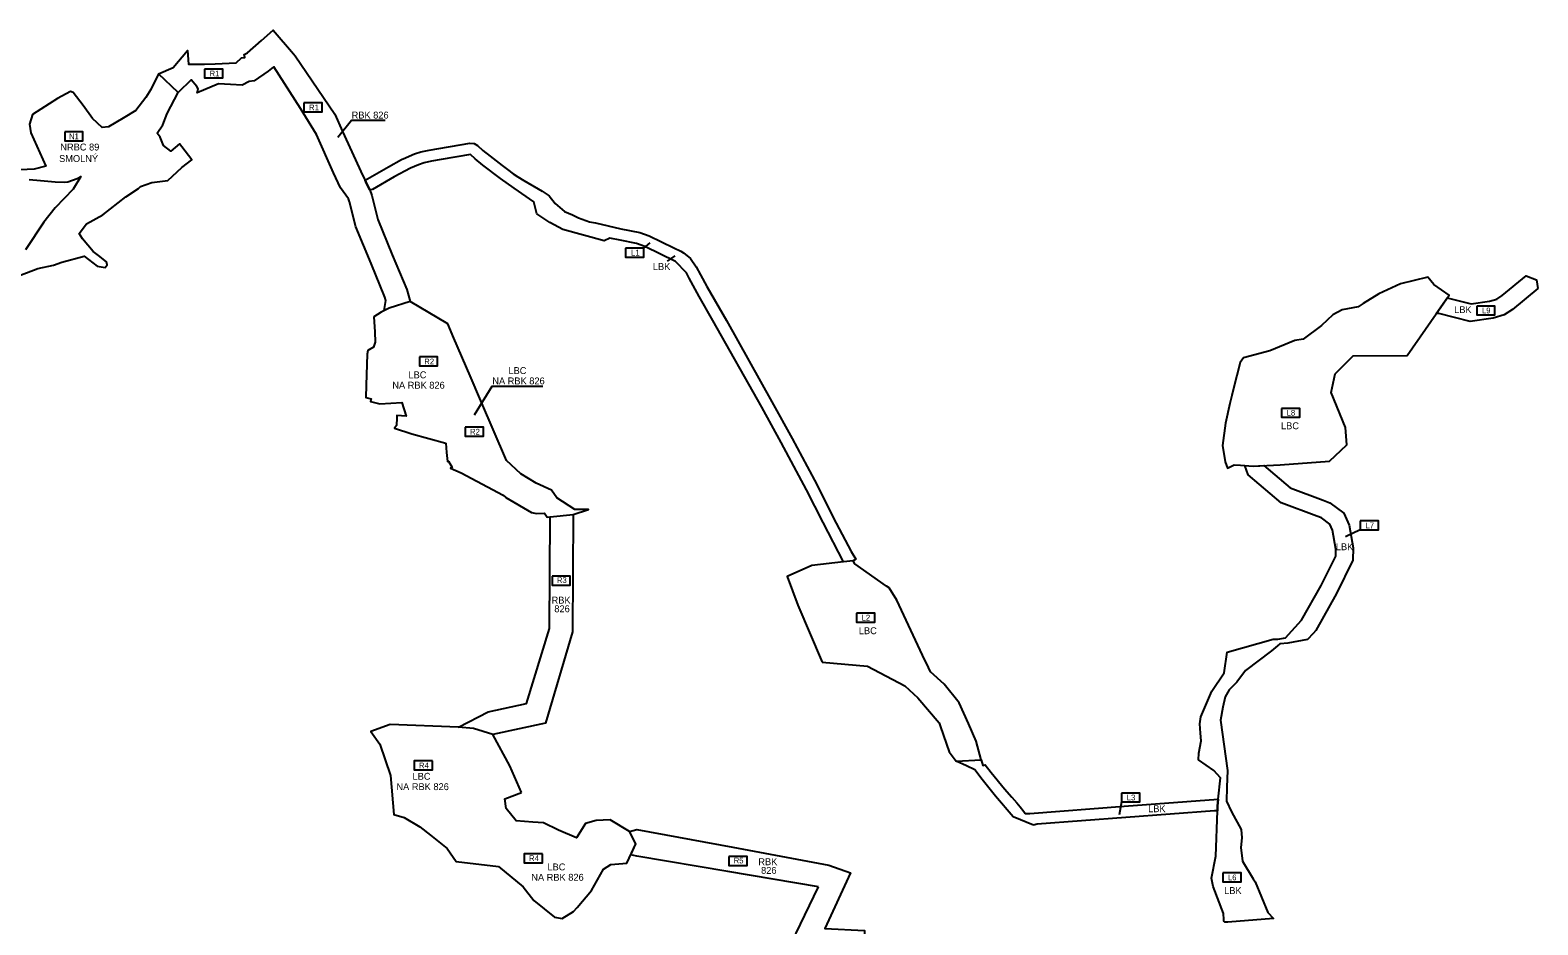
# Model space of a CAD drawing. Extents: x -546680 to -530218, y -1046521 to -1035695.
# Drawn here: x -542866 to -540248, y -1039689 to -1038135 of the extents above; entities that cross this region are included whole.
import ezdxf

# ---------------------------------------------------------------- set-up
doc = ezdxf.new("R2010")
doc.units = 0
for name, color, linetype in [('Vrstva 1', 7, 'Continuous'), ('Vrstva 18', 7, 'Continuous'), ('Vrstva 3', 7, 'Continuous'), ('Vrstva 30', 7, 'Continuous'), ('Vrstva 32', 7, 'Continuous'), ('Vrstva 33', 7, 'Continuous'), ('Vrstva 54', 7, 'Continuous'), ('Vrstva 82', 7, 'Continuous')]:
    doc.layers.add(name, color=color, linetype=linetype)

msp = doc.modelspace()

# ---------------------------------------------------------------- linework, layer by layer
at = {"layer": 'Vrstva 1'}
for points in [[(-542284.6, -1038396.1), (-542281.8, -1038401.7), (-542276.2, -1038412.8), (-542273, -1038422.6), (-542262.3, -1038464.5), (-542237.2, -1038525.6), (-542212.2, -1038585.7), (-542206.1, -1038606.5), (-542242.4, -1038618.3), (-542251.3, -1038622.5), (-542248.6, -1038604.8), (-542250, -1038599), (-542274.2, -1038540.9), (-542300.4, -1038477.1), (-542311.4, -1038433.8), (-542313.3, -1038428.1), (-542327.3, -1038409.3), (-542339.6, -1038383.2), (-542368.8, -1038316.9), (-542373.5, -1038309.2), (-542396.7, -1038271.2), (-542442.8, -1038198.9), (-542447, -1038202.1), (-542452.7, -1038206.8), (-542477.2, -1038223.2), (-542485.5, -1038224.6), (-542497.7, -1038230.9), (-542517.9, -1038229.8), (-542539.1, -1038228.8), (-542575.9, -1038244.5), (-542574.6, -1038237.3), (-542576.9, -1038233.4), (-542586.4, -1038221.8), (-542609.3, -1038243.8), (-542643.3, -1038211.5), (-542617.8, -1038200.5), (-542592.9, -1038170.8), (-542591.4, -1038194.5), (-542563.3, -1038194.5), (-542544.9, -1038193.7), (-542532.5, -1038193.1), (-542508.5, -1038192), (-542499.2, -1038183.2), (-542493.2, -1038183.1), (-542494.5, -1038177.9), (-542488.9, -1038174.9), (-542464.4, -1038153.3), (-542443.9, -1038135.4), (-542408.6, -1038176.6), (-542405.7, -1038180.1), (-542337.2, -1038281.4), (-542323.5, -1038311.4), (-542288.5, -1038388.2), (-542284.6, -1038396.1)], [(-542096.2, -1039348.1), (-542122.5, -1039345.9), (-542070.9, -1039319.5), (-542004.1, -1039304.9), (-541964.5, -1039174.3), (-541963.4, -1038980.4), (-541923.4, -1038976.8), (-541924, -1039078.6), (-541924.5, -1039180.3), (-541971.5, -1039338.7), (-542062.4, -1039358.6), (-542096.2, -1039348.1)], [(-541497.1, -1039623), (-541654.8, -1039596.4), (-541812.4, -1039569.9), (-541823.3, -1039567.6), (-541814.2, -1039548.4), (-541825.5, -1039527.1), (-541812.7, -1039523.3), (-541645.9, -1039554.4), (-541479.1, -1039585.5)], [(-541479.1, -1039585.5), (-541441.9, -1039599), (-541486, -1039695.6), (-541417.4, -1039699), (-541415.9, -1039747.1)], [(-541453, -1039757.1), (-541455.7, -1039732.7), (-541528.6, -1039734), (-541536.3, -1039704.6), (-541497.1, -1039623)]]:
    msp.add_lwpolyline(points, dxfattribs=at)
at = {"layer": 'Vrstva 18'}
for points in [[(-542884.3, -1038561.6), (-542852.6, -1038549.6), (-542825.5, -1038543.5), (-542811.2, -1038538.3), (-542772.5, -1038528.2), (-542749.6, -1038545.1), (-542735.8, -1038547.6), (-542732.4, -1038543), (-542733.3, -1038537.6), (-542747.2, -1038527), (-542756.6, -1038519.9), (-542775.1, -1038497.6), (-542781, -1038488.8), (-542768.4, -1038471.7), (-542739.9, -1038456.2), (-542700.2, -1038425.1), (-542677.8, -1038410.5), (-542674.6, -1038406.9), (-542654.7, -1038399.7), (-542626.9, -1038396.7), (-542602.8, -1038374), (-542585.5, -1038360.9), (-542602.6, -1038338), (-542606.6, -1038332.6), (-542621.9, -1038345.8), (-542634.5, -1038335.7), (-542640.1, -1038321.4), (-542645.3, -1038314.1), (-542635.8, -1038300), (-542628.4, -1038280), (-542609.3, -1038243.8), (-542643.3, -1038211.5), (-542656.6, -1038238.4), (-542665.1, -1038252.2), (-542682.8, -1038275.2), (-542704.4, -1038288.3), (-542730.3, -1038303.1), (-542740.8, -1038304.5), (-542757.6, -1038289.1), (-542774.1, -1038266.4), (-542791.2, -1038243.5), (-542796.1, -1038241.8), (-542818.6, -1038253.9), (-542862.1, -1038281.8), (-542867.4, -1038298.6), (-542864.8, -1038313.5), (-542838.9, -1038371.7), (-542859.1, -1038376.6), (-542883.4, -1038378)], [(-542867.8, -1038394.6), (-542847.8, -1038396.5), (-542822.6, -1038398.8), (-542806, -1038399.4), (-542800.4, -1038398.7), (-542784.3, -1038392.8), (-542778.1, -1038389.6), (-542791.3, -1038411.4), (-542822.9, -1038444.2), (-542842.2, -1038469), (-542873.9, -1038517.1)]]:
    msp.add_lwpolyline(points, dxfattribs=at)
at = {"layer": 'Vrstva 3'}
msp.add_line((-541759.3, -1038536.4), (-541746.1, -1038527.2), dxfattribs=at)
for points in [[(-542249.8, -1038292.3), (-542308.3, -1038292.3), (-542331.8, -1038321.8)], [(-541975.6, -1038754), (-542064.4, -1038754), (-542095.1, -1038803.9)]]:
    msp.add_lwpolyline(points, dxfattribs=at)
at = {"layer": 'Vrstva 30'}
for points in [[(-542563.2, -1038202.9), (-542563.2, -1038218.4), (-542531.5, -1038218.4), (-542531.5, -1038202.9), (-542563.2, -1038202.9)], [(-542390.6, -1038261.9), (-542390.6, -1038277.4), (-542358.9, -1038277.4), (-542358.9, -1038261.9), (-542390.6, -1038261.9)], [(-542806.1, -1038312), (-542806.1, -1038327.5), (-542774.4, -1038327.5), (-542774.4, -1038312), (-542806.1, -1038312)], [(-541959.9, -1039083.5), (-541959.9, -1039099), (-541928.2, -1039099), (-541928.2, -1039083.5), (-541959.9, -1039083.5)], [(-541652.9, -1039570.6), (-541652.9, -1039586.2), (-541621.2, -1039586.2), (-541621.2, -1039570.6), (-541652.9, -1039570.6)]]:
    msp.add_lwpolyline(points, dxfattribs=at)
at = {"layer": 'Vrstva 32'}
for points in [[(-540764.3, -1038890.9), (-540742.5, -1038892.4), (-540695.8, -1038890.1), (-540609.7, -1038884.2), (-540579.7, -1038855.5), (-540581.9, -1038825.5), (-540607.2, -1038764.7), (-540599.9, -1038732), (-540568.7, -1038701.1), (-540475, -1038700.3), (-540402.2, -1038595.5), (-540429, -1038577), (-540439.3, -1038564.1), (-540486.8, -1038575.7), (-540524.1, -1038593.1), (-540551.3, -1038610.1), (-540560.2, -1038615.7), (-540588, -1038621.1), (-540604.4, -1038629.6), (-540623.7, -1038648.1), (-540655.8, -1038671.8), (-540670.3, -1038674.4), (-540713.8, -1038692.2), (-540759.5, -1038704.5), (-540765.3, -1038712.8), (-540776.5, -1038757.7), (-540779.5, -1038769.7), (-540783, -1038784), (-540790.8, -1038818.1), (-540795.5, -1038856.8), (-540791.1, -1038885.2), (-540787.2, -1038896), (-540778.9, -1038891.8), (-540775.6, -1038890.1), (-540764.3, -1038890.9)], [(-542144.5, -1038852.9), (-542143, -1038869), (-542141.5, -1038884.4), (-542139.7, -1038884.2), (-542133.2, -1038895.2), (-542136.2, -1038896.3), (-542117.8, -1038904.3), (-542044.9, -1038943.2), (-542039.9, -1038946.9), (-541995.5, -1038972.9), (-541986.7, -1038974.7), (-541973, -1038974.4), (-541968.5, -1038980.9), (-541963.4, -1038980.4), (-541923.4, -1038976.8), (-541896.5, -1038968.1), (-541920.4, -1038968.1), (-541951.5, -1038947.8), (-541960.6, -1038934.5), (-541987.3, -1038921.9), (-542013.8, -1038905.7), (-542038.9, -1038882.8), (-542083.5, -1038779.2), (-542102.2, -1038735.7), (-542130.3, -1038670.2), (-542140.9, -1038645.5), (-542206.1, -1038606.5), (-542242.4, -1038618.3), (-542256.8, -1038625.1), (-542269.1, -1038633.3), (-542267.3, -1038659.4), (-542267.2, -1038677), (-542270, -1038686.2), (-542279.7, -1038691.8), (-542280.9, -1038698.3), (-542282.4, -1038752.2), (-542283, -1038773.4), (-542274.1, -1038775.9), (-542274.9, -1038780.5), (-542258.9, -1038784.2), (-542220.8, -1038782.2), (-542213, -1038805.8), (-542229.1, -1038804.6), (-542229.3, -1038808.6), (-542230.1, -1038821.9), (-542233.7, -1038826.6), (-542203.2, -1038836.2), (-542144.5, -1038852.9)], [(-541508.8, -1039064.9), (-541551.8, -1039084.4), (-541533.2, -1039134.2)], [(-541379.1, -1039101.1), (-541434.1, -1039062.1), (-541437.3, -1039057.1), (-541453.7, -1039058.9), (-541508.8, -1039064.9)], [(-541316.4, -1039221), (-541361.3, -1039125.5), (-541374.8, -1039104.1), (-541379.1, -1039101.1)], [(-541533.2, -1039134.2), (-541490.9, -1039233.1)], [(-541490.9, -1039233.1), (-541411.9, -1039239.8), (-541347.4, -1039274.2), (-541324.8, -1039295.1)], [(-541306.5, -1039242.1), (-541316.4, -1039221)], [(-541223.6, -1039370.3), (-541236.9, -1039339.5), (-541253, -1039303.7), (-541278.9, -1039271.4), (-541303, -1039249.5), (-541306.5, -1039242.1)], [(-541324.8, -1039295.1), (-541287.8, -1039338.2), (-541285.6, -1039345.3), (-541270.3, -1039388.7), (-541258, -1039405.2), (-541214.8, -1039402.4), (-541223.6, -1039370.3)], [(-542012.9, -1039459.2), (-542033.1, -1039412.8), (-542062.4, -1039358.6), (-542096.2, -1039348.1), (-542122.5, -1039345.9), (-542241, -1039341.3), (-542274.7, -1039353.4), (-542259, -1039375.2), (-542240.4, -1039429.6), (-542234.7, -1039497.8), (-542216.8, -1039502.6), (-542189.2, -1039518.9), (-542170.7, -1039533.6)], [(-542052.9, -1039587.9), (-542010.1, -1039623.4), (-541991.3, -1039646.9), (-541955.5, -1039676.1), (-541942.2, -1039678.2), (-541922.5, -1039665.9), (-541916.1, -1039658.8), (-541891.1, -1039629.8), (-541870.4, -1039592.2), (-541857.7, -1039584.2), (-541830.3, -1039582.2), (-541814.2, -1039548.4), (-541825.5, -1039527.1), (-541858.7, -1039507), (-541883.2, -1039508.2), (-541901.9, -1039513.1), (-541917.7, -1039537.9), (-541948.9, -1039524.7), (-541974.5, -1039511.9), (-541993.3, -1039510.6), (-542022.2, -1039508.8), (-542039.7, -1039487.1), (-542041.8, -1039470.2), (-542012.9, -1039459.2)], [(-542170.7, -1039533.6), (-542141.8, -1039556.7), (-542126.6, -1039579.4), (-542052.9, -1039587.9)]]:
    msp.add_lwpolyline(points, dxfattribs=at)
at = {"layer": 'Vrstva 33'}
msp.add_lwpolyline([(-542271.9, -1038411.9), (-542276.2, -1038412.8), (-542281.8, -1038401.7), (-542284.6, -1038396.1), (-542244, -1038372.8), (-542221.3, -1038360.3), (-542214.6, -1038356.9), (-542208.2, -1038354), (-542198.6, -1038350.4), (-542187.9, -1038346.8), (-542173.2, -1038343.6), (-542102.7, -1038331.6), (-542094.9, -1038332.4), (-542089.2, -1038335.5), (-542080, -1038344.3), (-542067.6, -1038354.4), (-542046.5, -1038370.4), (-542037.5, -1038377.2), (-542027.3, -1038384.7), (-542019.1, -1038390.4), (-542009.1, -1038396.7), (-541977.1, -1038415.3), (-541965, -1038422.9), (-541954.2, -1038436.3), (-541938.1, -1038450.1), (-541924.4, -1038456), (-541913.7, -1038461.6), (-541894.6, -1038468.1), (-541884.7, -1038470.1), (-541840.2, -1038480.7), (-541807.7, -1038486.8), (-541791.1, -1038492.6), (-541748.3, -1038513.3), (-541736.4, -1038519.3), (-541731.5, -1038522), (-541719.5, -1038531.9), (-541709.7, -1038546.4), (-541701.9, -1038560.1), (-541690.9, -1038580.8), (-541656.7, -1038639.9), (-541578, -1038780.7), (-541543.2, -1038844.3), (-541516.7, -1038893.1), (-541500.1, -1038924.3), (-541471.5, -1038981.6), (-541440.4, -1039040.7), (-541432.5, -1039054.2), (-541437.3, -1039057.1), (-541453.7, -1039058.9), (-541489.3, -1038990.7), (-541517.8, -1038933.5), (-541562.1, -1038851.5), (-541595.5, -1038790.4), (-541680.7, -1038639.6), (-541704.3, -1038597.8), (-541721.8, -1038565.9), (-541726.7, -1038557), (-541745.8, -1038536.9), (-541798.7, -1038511.1), (-541813.1, -1038506.1), (-541841.4, -1038500.3), (-541859.4, -1038496.6), (-541869.1, -1038501.1), (-541940.9, -1038481.6), (-541963.9, -1038469.4), (-541986.1, -1038454.4), (-541991.4, -1038433.3), (-542025.7, -1038409.7), (-542049.4, -1038393.3), (-542080.1, -1038370.1), (-542093.5, -1038359.1), (-542101.4, -1038351.5), (-542152.6, -1038360.2), (-542169.3, -1038363.2), (-542181.8, -1038366), (-542192, -1038369.3), (-542205.9, -1038375), (-542234.2, -1038390.3)], close=True, dxfattribs=at)
for points in [[(-540248.2, -1038584.2), (-540292.3, -1038620.3), (-540306.7, -1038629.8), (-540325.5, -1038635.7), (-540365.7, -1038641.2), (-540420.3, -1038627.3), (-540424.6, -1038627.6), (-540405.5, -1038600.1), (-540363.9, -1038610.6), (-540332.1, -1038606.3), (-540319.7, -1038602.4), (-540310.1, -1038596.1), (-540268.5, -1038562.1), (-540250.7, -1038568.9), (-540248.2, -1038584.2)], [(-540707.8, -1039193), (-540699.8, -1039193.1), (-540686.2, -1039190.9), (-540658.3, -1039160.2), (-540624.3, -1039100), (-540599.2, -1039048.7), (-540598.7, -1039036.7), (-540604.9, -1039004), (-540609.6, -1038993.3), (-540624.1, -1038982.5), (-540631.9, -1038979.4), (-540693.8, -1038956.2), (-540750.9, -1038907.8), (-540756.8, -1038891.4), (-540742.5, -1038892.4), (-540723.8, -1038891.5), (-540678.3, -1038930), (-540621, -1038951.4), (-540609.4, -1038956.1), (-540585.3, -1038974), (-540576.1, -1038995.1), (-540568.6, -1039034.4), (-540569.4, -1039056.1), (-540597.7, -1039114), (-540633.8, -1039177.9), (-540638.4, -1039183), (-540648.4, -1039193.9), (-540682.1, -1039200), (-540695.5, -1039201.1), (-540696.4, -1039201.2), (-540700.5, -1039204.7), (-540710.4, -1039213.2), (-540756.1, -1039247.6), (-540770.9, -1039268), (-540784.1, -1039281.3), (-540791, -1039293.4), (-540795.1, -1039311), (-540799.2, -1039334), (-540787.1, -1039421.4), (-540788, -1039450.1), (-540789, -1039474.2), (-540780.2, -1039493), (-540763.2, -1039523.7), (-540762.2, -1039537.8), (-540764.2, -1039554.8), (-540761.1, -1039578.7), (-540742.5, -1039609.1), (-540739.3, -1039614.4), (-540717.3, -1039667.5), (-540707.2, -1039678.1), (-540786.5, -1039684.4), (-540791.7, -1039684.8), (-540792.7, -1039683.6), (-540793.4, -1039682.3), (-540793.6, -1039679.6), (-540794, -1039669.3), (-540812, -1039622.7), (-540814.7, -1039607.9), (-540807.6, -1039569.8), (-540804.7, -1039490.9), (-540804.4, -1039482.9), (-540803.1, -1039470.7), (-540799.1, -1039433.7), (-540810.6, -1039420.9), (-540837.7, -1039402.8), (-540837.1, -1039390.9), (-540832.8, -1039369.8), (-540833.9, -1039356.4), (-540835.2, -1039340.1), (-540833.1, -1039327.7), (-540814.2, -1039283.2), (-540792.6, -1039251.5), (-540787.8, -1039215.8), (-540707.8, -1039193)], [(-541240.5, -1039413.2), (-541258, -1039405.2), (-541214.8, -1039402.4), (-541212.1, -1039412.2), (-541207.8, -1039411), (-541197.2, -1039424.8), (-541174.4, -1039453.2), (-541161.6, -1039467.4), (-541152.8, -1039477.5), (-541147.2, -1039484.2), (-541140.9, -1039492.3), (-541138.3, -1039496)], [(-541124.1, -1039516.3), (-541159.3, -1039501.5), (-541189.8, -1039465.9), (-541213, -1039437), (-541225.8, -1039419.9), (-541240.5, -1039413.2)], [(-541138.3, -1039496), (-541130.4, -1039495.6), (-540966.7, -1039483.2), (-540803.1, -1039470.7)], [(-540803.1, -1039470.7), (-540804.4, -1039482.9), (-540804.7, -1039490.9), (-540809.9, -1039491.3), (-540963.7, -1039503), (-541117.4, -1039514.6), (-541124.1, -1039516.3)]]:
    msp.add_lwpolyline(points, dxfattribs=at)
at = {"layer": 'Vrstva 54'}
for p, q in [((-541800.6, -1038514.1), (-541789.6, -1038505)), ((-540556.5, -1039003.3), (-540581.9, -1039015.2)), ((-540971.2, -1039475.8), (-540975.3, -1039498.3))]:
    msp.add_line(p, q, dxfattribs=at)
for points in [[(-541832.3, -1038514.1), (-541832.3, -1038529.6), (-541800.6, -1038529.6), (-541800.6, -1038514.1), (-541832.3, -1038514.1)], [(-540354.3, -1038614.5), (-540354.3, -1038630), (-540322.6, -1038630), (-540322.6, -1038614.5), (-540354.3, -1038614.5)], [(-542190.2, -1038703), (-542190.2, -1038718.5), (-542158.5, -1038718.5), (-542158.5, -1038703), (-542190.2, -1038703)], [(-540693.4, -1038792.2), (-540693.4, -1038807.7), (-540661.7, -1038807.7), (-540661.7, -1038792.2), (-540693.4, -1038792.2)], [(-542110.6, -1038825), (-542110.6, -1038840.5), (-542078.9, -1038840.5), (-542078.9, -1038825), (-542110.6, -1038825)], [(-540556.5, -1038987.8), (-540556.5, -1039003.3), (-540524.8, -1039003.3), (-540524.8, -1038987.8), (-540556.5, -1038987.8)], [(-541431.4, -1039148), (-541431.4, -1039163.5), (-541399.7, -1039163.5), (-541399.7, -1039148), (-541431.4, -1039148)], [(-542167.5, -1039404.6), (-542199.2, -1039404.6), (-542199.2, -1039420.2), (-542167.5, -1039420.2), (-542167.5, -1039404.6)], [(-540971.2, -1039460.2), (-540971.2, -1039475.8), (-540939.5, -1039475.8), (-540939.5, -1039460.2), (-540971.2, -1039460.2)], [(-541976.3, -1039565.7), (-542008, -1039565.7), (-542008, -1039581.3), (-541976.3, -1039581.3), (-541976.3, -1039565.7)], [(-540795.3, -1039599), (-540795.3, -1039614.5), (-540763.6, -1039614.5), (-540763.6, -1039599), (-540795.3, -1039599)]]:
    msp.add_lwpolyline(points, dxfattribs=at)

# ---------------------------------------------------------------- texts
at = {"layer": 'Vrstva 3'}
for s, p in [('RBK 826', (-542307.9, -1038288.9)), ('NRBC 89', (-542813.7, -1038344.4)), ('SMOLNÝ', (-542815.8, -1038364.4)), ('LBK', (-541784.8, -1038551.9)), ('LBK', (-540393.5, -1038626.9)), ('LBC', (-542209.2, -1038740)), ('LBC', (-542035.6, -1038732.6)), ('NA RBK 826', (-542237.2, -1038758)), ('NA RBK 826', (-542063.6, -1038750.6)), ('LBC', (-540694.1, -1038828.5)), ('LBK', (-540599, -1039038.6)), ('RBK', (-541960.7, -1039131.3)), ('826', (-541955.9, -1039146.3)), ('LBC', (-541427.2, -1039184.4)), ('LBC', (-542202.1, -1039437.2)), ('NA RBK 826', (-542230.1, -1039455.2)), ('LBK', (-540924.9, -1039493.5)), ('RBK', (-541601.7, -1039585.6)), ('LBC', (-541967.9, -1039594.6)), ('826', (-541596.9, -1039600.6)), ('NA RBK 826', (-541995.9, -1039612.6)), ('LBK', (-540792.9, -1039635.6))]:
    msp.add_text(s, height=12, dxfattribs=at).set_placement(p)
at = {"layer": 'Vrstva 54'}
for s, p in [('L1', (-541822.8, -1038526.9)), ('L9', (-540345.3, -1038627.2)), ('R2', (-542181.8, -1038715.8)), ('L8', (-540684.4, -1038804.9)), ('R2', (-542102.3, -1038837.8)), ('L7', (-540547.5, -1039000.5)), ('L2', (-541422.4, -1039160.7)), ('R4', (-542190.9, -1039417.4)), ('L3', (-540962, -1039473)), ('R4', (-541999.8, -1039578.5)), ('L6', (-540786.3, -1039611.8))]:
    msp.add_text(s, height=10, dxfattribs=at).set_placement(p)
at = {"layer": 'Vrstva 82'}
for s, p in [('R1', (-542554.5, -1038215.7)), ('R1', (-542381.8, -1038274.7)), ('N1', (-542798.6, -1038324.8)), ('R3', (-541951.5, -1039095.4)), ('R5', (-541644.5, -1039582.5))]:
    msp.add_text(s, height=10, dxfattribs=at).set_placement(p)

doc.saveas('drawing.dxf')
